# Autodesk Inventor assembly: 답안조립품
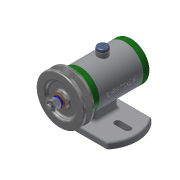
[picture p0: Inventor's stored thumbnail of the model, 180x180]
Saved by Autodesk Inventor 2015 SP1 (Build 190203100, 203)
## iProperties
Created: 2017-12
Part Number: 답안조립품
Document SubType Name: Assembly
Designer: C04
Author: C04
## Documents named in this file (14)
- C:\Users\C04\Desktop\471207V1022\답안조립품.iam
- C:\Users\C04\Desktop\471207V1022\1-본체.ipt
- C:\Users\C04\Desktop\471207V1022\2-베어링 15 x 32 x 9.ipt
- C:\Users\C04\Desktop\471207V1022\3-뒤커버.ipt
- C:\Users\C04\Desktop\471207V1022\4-앞커버.ipt
- C:\Users\C04\Desktop\471207V1022\5-오일 실 15 25 7.ipt
- C:\Users\C04\Desktop\471207V1022\6-볼트 M4 x 12.ipt
- C:\Users\C04\Desktop\471207V1022\7-축.ipt
- C:\Users\C04\Desktop\471207V1022\8-키 3 x 3 x 12.ipt
- C:\Users\C04\Desktop\471207V1022\9-V벨트풀리.ipt
- C:\Users\C04\Desktop\471207V1022\10-와셔 8x17.ipt
- C:\Users\C04\Desktop\471207V1022\11-스프링와셔 8.ipt
- C:\Users\C04\Desktop\471207V1022\12-너트 M 8.ipt
- C:\Users\C04\Desktop\471207V1022\13-고무캡.ipt
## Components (12 placed, 11 different names)
1. 1-본체:1
2. 3-뒤커버:1
3. 4-앞커버:1
4. 5-오일 실 15 25 7:1
5. 7-축:1 — 각도:1
6. 8-키 3 x 3 x 12:1 — 각도:1, 각도:2
7. 9-V벨트풀리:1 — 각도:2
8. 10-와셔 8x17:1
9. 11-스프링와셔 8:1
10. 12-너트 M 8:1
11. 13-고무캡:1
12. 12-너트 M 8:2
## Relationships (2: Angle 2)
- 각도:1 [Angle]: 7-축:1 ↔ 8-키 3 x 3 x 12:1
- 각도:2 [Angle]: 8-키 3 x 3 x 12:1 ↔ 9-V벨트풀리:1
